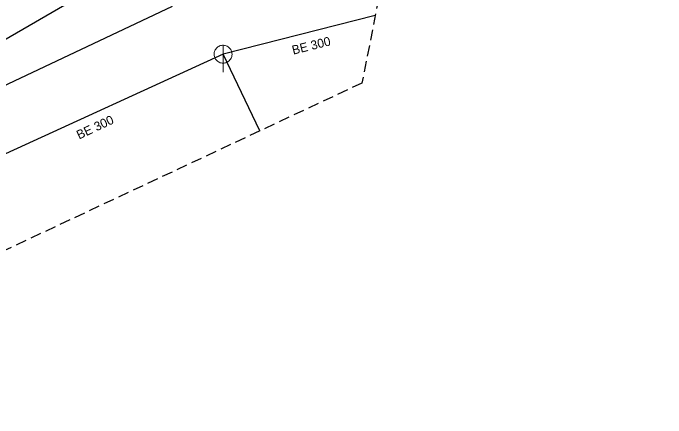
# Model space of a CAD drawing. Extents: x -688693 to -688474, y -974081 to -973994.
# Drawn here: x -688620.1 to -688547.3, y -974081 to -974035.9 of the extents above; entities that cross this region are included whole.
import ezdxf

# ---------------------------------------------------------------- set-up
doc = ezdxf.new("R2010")
doc.units = 0
doc.header["$LTSCALE"] = 0.4
doc.linetypes.add('MEDIUM_DASHED', pattern=[4.5, 3, -1.5])
for name, color, linetype, lineweight in [('1', 7, 'MEDIUM_DASHED', 25), ('14', 7, 'Continuous', 25), ('17', 7, 'Continuous', 25), ('22', 7, 'Continuous', 13)]:
    doc.layers.add(name, color=color, linetype=linetype, lineweight=lineweight)

msp = doc.modelspace()

# ---------------------------------------------------------------- linework, layer by layer
at = {"layer": '1'}
msp.add_lwpolyline([(-688692.931, -974052.713), (-688674.241, -974042.463), (-688662.987, -974051.708), (-688552.455, -973994.231), (-688543.813, -974004.28), (-688496.988, -974010.309), (-688488.949, -974009.103), (-688474.077, -974014.529), (-688476.69, -974033.621), (-688494.978, -974032.616), (-688541.804, -974022.367), (-688555.67, -974019.352), (-688572.552, -974027.19), (-688578.982, -974032.415), (-688581.193, -974043.669), (-688636.057, -974069.393), (-688655.149, -974067.182), (-688651.532, -974076.829), (-688666.202, -974081.049), (-688669.82, -974071.805), (-688685.294, -974080.647), (-688689.113, -974064.369), (-688682.883, -974060.751)], close=True, dxfattribs=at)
at = {"layer": '14'}
for p, q in [((-688658.556, -974060.52), (-688598.575, -974025.813)), ((-688579.71, -974036.118), (-688596.688, -974040.453)), ((-688596.688, -974040.453), (-688625, -974053.399)), ((-688592.59, -974049.013), (-688596.688, -974040.453))]:
    msp.add_line(p, q, dxfattribs=at)
at = {"layer": '17'}
msp.add_lwpolyline([(-688652.752, -974058.945), (-688651.228, -974058.19), (-688641.695, -974053.653), (-688634.831, -974050.489), (-688629.499, -974047.91), (-688602.322, -974035.098)], dxfattribs=at)
at = {"layer": '22'}
msp.add_line((-688596.688, -974042.453), (-688596.687, -974039.453), dxfattribs=at)
msp.add_lwpolyline([(-688595.688, -974040.453), (-688595.693, -974040.344), (-688595.711, -974040.236), (-688595.741, -974040.13), (-688595.781, -974040.029), (-688595.833, -974039.932), (-688595.895, -974039.842), (-688595.967, -974039.759), (-688596.047, -974039.685), (-688596.135, -974039.619), (-688596.229, -974039.564), (-688596.329, -974039.519), (-688596.434, -974039.486), (-688596.541, -974039.464), (-688596.65, -974039.454), (-688596.76, -974039.456), (-688596.868, -974039.47), (-688596.975, -974039.495), (-688597.078, -974039.532), (-688597.176, -974039.581), (-688597.268, -974039.639), (-688597.354, -974039.708), (-688597.431, -974039.785), (-688597.5, -974039.871), (-688597.559, -974039.963), (-688597.607, -974040.061), (-688597.644, -974040.164), (-688597.67, -974040.271), (-688597.684, -974040.379), (-688597.687, -974040.489), (-688597.677, -974040.598), (-688597.656, -974040.705), (-688597.622, -974040.809), (-688597.578, -974040.909), (-688597.523, -974041.004), (-688597.457, -974041.092), (-688597.383, -974041.172), (-688597.3, -974041.244), (-688597.21, -974041.306), (-688597.114, -974041.358), (-688597.012, -974041.399), (-688596.907, -974041.429), (-688596.799, -974041.447), (-688596.689, -974041.453), (-688596.58, -974041.447), (-688596.472, -974041.429), (-688596.367, -974041.4), (-688596.265, -974041.359), (-688596.168, -974041.307), (-688596.078, -974041.245), (-688595.995, -974041.174), (-688595.92, -974041.094), (-688595.855, -974041.006), (-688595.799, -974040.912), (-688595.755, -974040.812), (-688595.721, -974040.708), (-688595.699, -974040.6), (-688595.689, -974040.491)], close=True, dxfattribs=at)

# ---------------------------------------------------------------- texts
at = {"layer": '1'}
for rotation, p in [(14, (-688588.859, -974040.503)), (25, (-688612.746, -974049.979))]:
    msp.add_text('BE 300', height=1, rotation=rotation, dxfattribs=at).set_placement(p)

doc.saveas('drawing.dxf')
